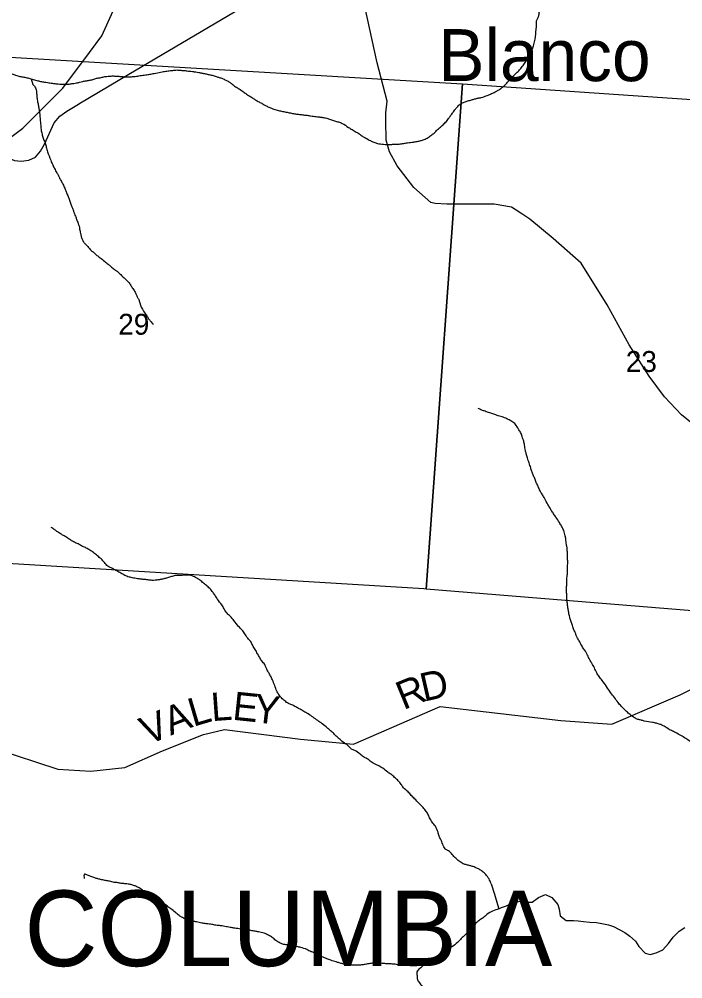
# Model space of a CAD drawing. Extents: x -15 to 405, y -40 to 87.
# Drawn here: x 5.48 to 6.81, y 18.018 to 19.941 of the extents above; entities that cross this region are included whole.
import ezdxf

# ---------------------------------------------------------------- set-up
doc = ezdxf.new("R2010")
doc.units = 0
for name, color, linetype in [('GM_P_State_Location', 7, 'Continuous'), ('GM_X_Adjacent_County_Text', 7, 'Continuous'), ('GM_X_Airport_Location_Class_2', 7, 'Continuous'), ('GM_X_County_Road', 7, 'Continuous'), ('GM_X_County_Road_Text', 7, 'Continuous'), ('GM_X_Minor_River', 7, 'Continuous'), ('GM_X_State_Location', 7, 'Continuous'), ('GM_X_Township_ROW', 7, 'Continuous'), ('GM_X_Township_Text', 7, 'Continuous'), ('GM_X_Unincorporated_Location', 7, 'Continuous')]:
    doc.layers.add(name, color=color, linetype=linetype)

msp = doc.modelspace()

# ---------------------------------------------------------------- linework, layer by layer
at = {"layer": 'GM_P_State_Location'}
msp.add_lwpolyline([(5.4305, 18.4794), (5.557, 18.4381), (5.6234, 18.4343), (5.6914, 18.4412), (5.767, 18.475), (5.8493, 18.5078), (5.8915, 18.518), (6.0434, 18.4984), (6.1497, 18.4886), (6.324, 18.5635), (6.5659, 18.5359), (6.6681, 18.5284), (6.8048, 18.5869), (6.8593, 18.6138)], dxfattribs=at)
at = {"layer": 'GM_X_Adjacent_County_Text'}
for points in [[(5.504, 19.8214), (5.507, 19.8106)], [(6.4257, 18.2083), (6.4324, 18.1875), (6.4386, 18.1672), (6.4414, 18.1583)], [(6.4414, 18.1583), (6.4465, 18.161), (6.4564, 18.164), (6.4696, 18.1701), (6.4833, 18.1739), (6.4954, 18.1717), (6.5083, 18.1717), (6.5211, 18.1812), (6.5348, 18.1869), (6.5477, 18.1809), (6.5594, 18.1669), (6.5621, 18.1574), (6.564, 18.1445), (6.5765, 18.135), (6.5909, 18.1347), (6.6004, 18.1343), (6.611, 18.1328), (6.6239, 18.1317), (6.6371, 18.1306), (6.6481, 18.1287), (6.6614, 18.1265), (6.6712, 18.1227), (6.6826, 18.117), (6.694, 18.1106), (6.7039, 18.1038), (6.7152, 18.0932), (6.7221, 18.083), (6.7346, 18.0693), (6.7448, 18.0667), (6.7569, 18.0698), (6.7698, 18.0758), (6.7812, 18.0888), (6.7906, 18.1013), (6.8027, 18.1134), (6.8145, 18.121)]]:
    msp.add_lwpolyline(points, dxfattribs=at)
for points in [[(6.0573, 19.7487), (6.0641, 19.7474), (6.0751, 19.7459), (6.0811, 19.7453), (6.0879, 19.7443), (6.0962, 19.7429), (6.1041, 19.7403), (6.1116, 19.7374), (6.1199, 19.7353), (6.1274, 19.7324), (6.14, 19.7243), (6.1471, 19.7199), (6.1553, 19.7151), (6.162, 19.7111), (6.1679, 19.7067), (6.1746, 19.7031), (6.1839, 19.6978), (6.1907, 19.6949), (6.1982, 19.6924), (6.2038, 19.6911), (6.2103, 19.6905), (6.2163, 19.6899), (6.2228, 19.6901), (6.2304, 19.6906), (6.2414, 19.691), (6.2509, 19.6922), (6.2582, 19.6935), (6.2643, 19.6944), (6.27, 19.695), (6.2776, 19.6962), (6.2849, 19.6979), (6.2914, 19.6999), (6.2995, 19.7042), (6.3069, 19.7093), (6.3128, 19.7144), (6.3206, 19.7218), (6.3277, 19.728), (6.3347, 19.7346), (6.3407, 19.7424), (6.3447, 19.7479), (6.3494, 19.7542), (6.3542, 19.7609), (6.3589, 19.7665), (6.3656, 19.7723), (6.3718, 19.7752), (6.3794, 19.7776), (6.3867, 19.7796), (6.3928, 19.7813), (6.3997, 19.783), (6.4062, 19.7843), (6.4162, 19.7877), (6.4231, 19.7905), (6.4304, 19.7937), (6.437, 19.7973), (6.4432, 19.8009), (6.4502, 19.8064), (6.4561, 19.8119), (6.4616, 19.8178), (6.4679, 19.8248), (6.4769, 19.8336), (6.4828, 19.8395), (6.4884, 19.8461), (6.494, 19.8543), (6.5, 19.8636), (6.5052, 19.8725), (6.5089, 19.8815), (6.5115, 19.8902), (6.5141, 19.9011), (6.5151, 19.9083), (6.5157, 19.9159), (6.5164, 19.923), (6.517, 19.9299), (6.5168, 19.9363), (6.5189, 19.942), (6.5214, 19.9479), (6.5223, 19.9548), (6.5237, 19.9615), (6.5258, 19.9672), (6.5306, 19.9746), (6.5368, 19.9782), (6.546, 19.9817), (6.5537, 19.9841), (6.5598, 19.9866), (6.5676, 19.9909), (6.5758, 19.9974), (6.5844, 20.0047), (6.5903, 20.0106), (6.597, 20.0187), (6.6013, 20.0243), (6.6046, 20.0299), (6.6086, 20.0381), (6.6108, 20.0456), (6.6121, 20.0517), (6.6127, 20.0577), (6.6122, 20.0653), (6.6117, 20.0726), (6.6107, 20.0783)], [(5.28, 19.8679), (5.2943, 19.8728), (5.3045, 19.8732), (5.314, 19.8736), (5.3205, 19.8742), (5.3277, 19.8736), (5.3348, 19.8714), (5.3416, 19.8689), (5.3516, 19.8637), (5.361, 19.8584), (5.3715, 19.8543), (5.3925, 19.849), (5.4023, 19.8472), (5.4102, 19.845), (5.4238, 19.8415), (5.4313, 19.8397), (5.4411, 19.8379), (5.4487, 19.8361), (5.4569, 19.8336), (5.4652, 19.8314), (5.4727, 19.8293), (5.4814, 19.8267), (5.4893, 19.8253), (5.4968, 19.8235), (5.5055, 19.8209), (5.5149, 19.8184), (5.5228, 19.8166), (5.5304, 19.8152), (5.5364, 19.8142), (5.5466, 19.8127), (5.5553, 19.8117), (5.567, 19.8109), (5.5739, 19.8107), (5.5822, 19.8116), (5.5891, 19.8125), (5.5948, 19.8134), (5.601, 19.8151), (5.6071, 19.8164), (5.6136, 19.8177), (5.6201, 19.8187), (5.6277, 19.8203), (5.635, 19.8227), (5.6423, 19.824), (5.6495, 19.8257), (5.6579, 19.8269), (5.6663, 19.8274), (5.6754, 19.8271), (5.6833, 19.8264), (5.692, 19.8258), (5.7023, 19.8258), (5.7122, 19.8266), (5.7225, 19.8282), (5.7332, 19.8297), (5.7416, 19.831), (5.7507, 19.8326), (5.7633, 19.8352), (5.7691, 19.8361), (5.7782, 19.8377), (5.7877, 19.8386), (5.7961, 19.8394), (5.8037, 19.8388), (5.8124, 19.8381), (5.8211, 19.8371), (5.8272, 19.8365), (5.834, 19.8355), (5.8396, 19.8346), (5.846, 19.8332), (5.8532, 19.8318), (5.8607, 19.8301), (5.8686, 19.8283), (5.8765, 19.8257), (5.8825, 19.824), (5.8889, 19.8215), (5.8956, 19.8183), (5.9012, 19.815), (5.9068, 19.8111), (5.9134, 19.8059), (5.9209, 19.8015), (5.9294, 19.7955), (5.9357, 19.7911), (5.9439, 19.7859), (5.9506, 19.7815), (5.9569, 19.7775), (5.9644, 19.7735), (5.9707, 19.7698), (5.9767, 19.7666), (5.9838, 19.7637), (5.9902, 19.7612), (5.9999, 19.7582), (6.0078, 19.7564), (6.0169, 19.7546), (6.0256, 19.7528), (6.0335, 19.7514), (6.0414, 19.7504), (6.0497, 19.7494), (6.0573, 19.7487)], [(5.507, 19.8106), (5.5111, 19.8056), (5.5142, 19.7971), (5.515, 19.788), (5.5159, 19.78), (5.5175, 19.7715), (5.5191, 19.7635), (5.5204, 19.757), (5.521, 19.7505), (5.5218, 19.7403), (5.5229, 19.7288), (5.5241, 19.7174), (5.5261, 19.709), (5.5285, 19.7009), (5.532, 19.6928), (5.534, 19.6848), (5.5367, 19.6756), (5.543, 19.6587), (5.5469, 19.6494), (5.5508, 19.6417), (5.5551, 19.6336), (5.5587, 19.6274), (5.5615, 19.6216), (5.5654, 19.6142), (5.5694, 19.6065), (5.5725, 19.5988), (5.5753, 19.5919), (5.5789, 19.5842), (5.5813, 19.5765), (5.584, 19.5684), (5.5869, 19.5622), (5.5889, 19.5557), (5.5924, 19.5465), (5.5949, 19.5403), (5.5977, 19.5326), (5.5997, 19.5265), (5.601, 19.5204), (5.6027, 19.512), (5.6043, 19.5051), (5.6068, 19.4989), (5.61, 19.4931), (5.6159, 19.4872), (5.6221, 19.4798), (5.628, 19.4747), (5.6357, 19.4679), (5.642, 19.4632), (5.6513, 19.4557), (5.6579, 19.4501), (5.6635, 19.4458), (5.6701, 19.4402), (5.6761, 19.4362), (5.6816, 19.4311), (5.6882, 19.4244), (5.6956, 19.4177), (5.7014, 19.4107), (5.7054, 19.4049), (5.7101, 19.3975), (5.7137, 19.3909), (5.7161, 19.3851), (5.7194, 19.3793), (5.7214, 19.3728), (5.7292, 19.3558), (5.7346, 19.3484), (5.7382, 19.3422)], [(5.7382, 19.3422), (5.7426, 19.3364), (5.7488, 19.3297)], [(6.5777, 18.7853), (6.5772, 18.7933), (6.5771, 18.802), (6.5777, 18.81), (6.5782, 18.8248), (6.5792, 18.8327), (6.5791, 18.8411), (6.5794, 18.8494), (6.5793, 18.8578), (6.5792, 18.8658), (6.5787, 18.8738), (6.5782, 18.8821), (6.5769, 18.8886), (6.5757, 18.8989), (6.5745, 18.9058), (6.5714, 18.9165), (6.5671, 18.925), (6.5628, 18.9324), (6.5559, 18.9429), (6.5512, 18.9499), (6.5465, 18.9569), (6.5419, 18.965), (6.5379, 18.9716), (6.5322, 18.9828), (6.5279, 18.9894), (6.5239, 18.996), (6.52, 19.0052), (6.5161, 19.013), (6.5133, 19.0207), (6.5102, 19.028), (6.5074, 19.0349), (6.5053, 19.0422), (6.5022, 19.0518), (6.4988, 19.0622), (6.4964, 19.0702), (6.4947, 19.0767), (6.4928, 19.0874), (6.4912, 19.0955), (6.488, 19.1047), (6.4849, 19.1132), (6.4806, 19.1198), (6.4748, 19.1291), (6.4674, 19.135), (6.46, 19.139), (6.4502, 19.1435), (6.4401, 19.1465), (6.4311, 19.1495), (6.4232, 19.152), (6.4138, 19.1554), (6.4071, 19.1579), (6.3999, 19.1608)], [(5.7921, 18.8261), (5.7848, 18.8241), (5.7768, 18.8217), (5.7695, 18.8196), (5.7626, 18.818), (5.7557, 18.8171), (5.7489, 18.8165), (5.7398, 18.8172), (5.7315, 18.8182), (5.7243, 18.8189), (5.7167, 18.8199), (5.7065, 18.8217), (5.6979, 18.8239), (5.6893, 18.8276), (5.6818, 18.832), (5.6736, 18.8365), (5.6643, 18.8414), (5.6557, 18.8466), (5.6492, 18.854), (5.6422, 18.8611), (5.6348, 18.8674), (5.627, 18.8737), (5.6196, 18.8782), (5.6125, 18.8822), (5.605, 18.8855), (5.598, 18.8895), (5.5905, 18.8928), (5.583, 18.8972), (5.5767, 18.9016), (5.57, 18.9056), (5.5637, 18.9093), (5.557, 18.9137), (5.5507, 18.9181), (5.544, 18.9228)], [(6.4257, 18.2083), (6.4229, 18.2156), (6.4168, 18.2253), (6.4098, 18.232), (6.4035, 18.2367), (6.3971, 18.2396), (6.39, 18.2429), (6.3836, 18.2446), (6.3768, 18.2464), (6.3701, 18.2485), (6.3619, 18.2541), (6.3549, 18.2596), (6.3479, 18.2674), (6.3402, 18.2745), (6.3339, 18.2786), (6.3289, 18.2878), (6.325, 18.2971), (6.3218, 18.3037), (6.3194, 18.3117), (6.3141, 18.3237), (6.3076, 18.3322), (6.3025, 18.3408), (6.2993, 18.3477), (6.2943, 18.3555), (6.2881, 18.3629), (6.2818, 18.3692), (6.2723, 18.379), (6.2657, 18.3857), (6.2595, 18.3927), (6.2502, 18.401), (6.2455, 18.4076), (6.2397, 18.4147), (6.2323, 18.4217), (6.2249, 18.4281), (6.2186, 18.4321), (6.209, 18.44), (6.1918, 18.4489), (6.1837, 18.4545), (6.1774, 18.4589), (6.1699, 18.4629), (6.1633, 18.4681), (6.1525, 18.4757), (6.1461, 18.4785), (6.1388, 18.4856), (6.1317, 18.4904), (6.1232, 18.4975), (6.1151, 18.5046), (6.1089, 18.5109), (6.1026, 18.5165), (6.0949, 18.5232), (6.0849, 18.5307), (6.076, 18.5371), (6.0667, 18.5439), (6.0567, 18.5503), (6.0485, 18.5551), (6.041, 18.5592), (6.0347, 18.5628), (6.0261, 18.5672), (6.0197, 18.5697), (6.0123, 18.5749), (6.0057, 18.5808), (6.0002, 18.5875), (5.9963, 18.5948), (5.9921, 18.6056), (5.9875, 18.6171), (5.9836, 18.6249), (5.9797, 18.6322), (5.975, 18.6411), (5.9722, 18.6477), (5.966, 18.6551), (5.9617, 18.6625), (5.9577, 18.6694), (5.9527, 18.6779), (5.948, 18.6857), (5.9448, 18.6926), (5.9379, 18.7009), (5.9321, 18.7094), (5.9263, 18.7172), (5.9197, 18.7242), (5.9102, 18.736), (5.9029, 18.7446), (5.8966, 18.7505), (5.8909, 18.7594), (5.8858, 18.7672), (5.8775, 18.7788), (5.8728, 18.7858), (5.8684, 18.7924), (5.8619, 18.8002), (5.8552, 18.8062), (5.8475, 18.8125), (5.8404, 18.8184), (5.8311, 18.8237), (5.8248, 18.8265), (5.8145, 18.8269), (5.8081, 18.8267), (5.7993, 18.8262), (5.7921, 18.8261)], [(7.1039, 18.1457), (7.1065, 18.169), (7.1065, 18.1789), (7.1059, 18.1853), (7.1058, 18.1922), (7.1061, 18.2017), (7.1051, 18.2177), (7.1032, 18.2276), (7.1002, 18.2414), (7.0975, 18.2517), (7.0952, 18.2621), (7.0915, 18.2751), (7.0883, 18.2836), (7.0827, 18.2967), (7.0788, 18.3044), (7.0752, 18.311), (7.0709, 18.318), (7.0662, 18.3253), (7.0611, 18.3331), (7.0553, 18.3413), (7.0506, 18.3479), (7.0444, 18.3553), (7.0356, 18.3659), (7.029, 18.3737), (7.0226, 18.3838), (7.0178, 18.3904), (7.0113, 18.3982), (7.0032, 18.4065), (6.9947, 18.4151), (6.9877, 18.421), (6.9773, 18.4282), (6.9699, 18.4326), (6.9595, 18.4391), (6.952, 18.4423), (6.9438, 18.4479), (6.9375, 18.4516), (6.93, 18.456), (6.9229, 18.4596), (6.9158, 18.4603), (6.9078, 18.4609), (6.8995, 18.4608), (6.893, 18.4614), (6.885, 18.4613), (6.8786, 18.4607), (6.8714, 18.4617), (6.8613, 18.4678), (6.8547, 18.4729), (6.8472, 18.4777), (6.8409, 18.4821), (6.8343, 18.4877), (6.825, 18.4937), (6.8161, 18.4997), (6.806, 18.5057), (6.7956, 18.5114), (6.7874, 18.5154), (6.7784, 18.5207), (6.771, 18.5251), (6.7646, 18.528), (6.7571, 18.5301), (6.7496, 18.5319), (6.733, 18.5347), (6.7266, 18.5364), (6.7202, 18.5378), (6.7134, 18.5411), (6.7045, 18.5474), (6.6972, 18.5538), (6.6869, 18.5643), (6.6803, 18.5718), (6.6734, 18.5815), (6.6654, 18.592), (6.6571, 18.6037), (6.6484, 18.6162), (6.6422, 18.624), (6.6375, 18.6313), (6.6329, 18.6414), (6.6279, 18.6503), (6.6235, 18.6576), (6.6193, 18.6669), (6.6132, 18.677), (6.6081, 18.6847), (6.6035, 18.6932), (6.5992, 18.7006), (6.5942, 18.7122), (6.5911, 18.7195), (6.5883, 18.7279), (6.5855, 18.7356), (6.5835, 18.7429), (6.5815, 18.7521), (6.5802, 18.7597), (6.579, 18.7681), (6.5781, 18.7761), (6.5777, 18.7853)], [(6.2909, 18.0451), (6.2848, 18.0458), (6.2764, 18.0441), (6.2665, 18.0441), (6.2582, 18.0447), (6.2502, 18.0454), (6.2434, 18.0456), (6.2336, 18.0471), (6.2253, 18.0477), (6.2184, 18.048), (6.2109, 18.0486), (6.198, 18.0494), (6.19, 18.0493), (6.1805, 18.0481), (6.1713, 18.0465), (6.1641, 18.0456), (6.1576, 18.0454), (6.1489, 18.0453), (6.1424, 18.0459), (6.1356, 18.0465), (6.1288, 18.0479), (6.1213, 18.05), (6.1149, 18.0518), (6.1044, 18.0551), (6.0965, 18.0581), (6.0868, 18.0622), (6.0782, 18.067), (6.0715, 18.0703), (6.0651, 18.0724), (6.0565, 18.0765), (6.0441, 18.0807), (6.037, 18.0825), (6.0291, 18.0846), (6.0193, 18.0861), (6.0098, 18.0868), (6.003, 18.0893), (5.9941, 18.0949), (5.9871, 18.1008), (5.9797, 18.1053), (5.9707, 18.1094), (5.9594, 18.112), (5.953, 18.1134), (5.9443, 18.1148), (5.9345, 18.1163), (5.9235, 18.1178), (5.9122, 18.1196), (5.905, 18.1206), (5.8952, 18.1225), (5.8835, 18.1244), (5.874, 18.1255), (5.8661, 18.1269), (5.8548, 18.1284), (5.8457, 18.1298), (5.8352, 18.1321), (5.8284, 18.1331), (5.8208, 18.1348), (5.8141, 18.1373), (5.8073, 18.1406), (5.8003, 18.145), (5.7929, 18.151), (5.7836, 18.1585), (5.7762, 18.164), (5.7685, 18.1704), (5.7592, 18.1768), (5.7506, 18.182), (5.7429, 18.1876), (5.7354, 18.192), (5.7279, 18.1953), (5.7205, 18.2001), (5.7138, 18.2034), (5.7074, 18.2058), (5.7002, 18.2076), (5.6915, 18.2086), (5.684, 18.2093), (5.6772, 18.2106), (5.6704, 18.2112), (5.661, 18.2135), (5.6538, 18.2148), (5.6447, 18.2167), (5.6376, 18.2184), (5.6312, 18.2201), (5.6233, 18.2231), (5.6169, 18.2256), (5.6106, 18.2277), (5.6103, 18.2189)], [(6.4414, 18.1583), (6.4176, 18.147), (6.4098, 18.1404), (6.4028, 18.1357), (6.3961, 18.1302), (6.3899, 18.1236), (6.3847, 18.1173), (6.3777, 18.1103), (6.3718, 18.104), (6.3643, 18.0971), (6.3561, 18.0886), (6.344, 18.0803), (6.3374, 18.0755), (6.3277, 18.0683), (6.3203, 18.0647), (6.3126, 18.06), (6.3052, 18.0553), (6.2971, 18.0495), (6.2905, 18.0448), (6.283, 18.0386), (6.2771, 18.0319), (6.2773, 18.0247), (6.2781, 18.0167), (6.2821, 18.0101), (6.2879, 18.0023), (6.2929, 17.9915), (6.2979, 17.9838), (6.3007, 17.9768), (6.3039, 17.9687), (6.3078, 17.961), (6.311, 17.9545), (6.3138, 17.9479), (6.317, 17.9406), (6.3194, 17.934), (6.3241, 17.9248), (6.3269, 17.9178), (6.3289, 17.9113), (6.3313, 17.9029)]]:
    msp.add_spline(points, degree=3, dxfattribs=at)
at = {"layer": 'GM_X_Airport_Location_Class_2'}
for points in [[(6.3688, 19.8114), (6.2955, 18.7989), (6.2908, 18.7993), (5.28, 18.8608), (5.3465, 19.8721)], [(6.3688, 19.8114), (7.3949, 19.7416), (7.3224, 18.7155), (6.2955, 18.7989)]]:
    msp.add_lwpolyline(points, close=True, dxfattribs=at)
at = {"layer": 'GM_X_State_Location'}
for points in [[(5.6204, 19.8745), (5.6452, 19.908), (5.7984, 20.246), (5.8576, 20.3778), (6.0106, 20.7189), (6.0897, 20.8941)], [(4.8734, 19.3513), (4.9332, 19.3808), (5.2102, 19.5467), (5.4005, 19.659), (5.4339, 19.6835), (5.4873, 19.7225), (5.5672, 19.8027), (5.6204, 19.8745)]]:
    msp.add_lwpolyline(points, dxfattribs=at)
at = {"layer": 'GM_X_Township_Text'}
for points in [[(5.5987, 19.771), (5.5992, 19.7713), (5.6997, 19.8308), (5.9115, 19.9562), (6.1383, 20.0943)], [(5.2723, 19.6212), (5.3223, 19.6433), (5.3458, 19.6658), (5.3621, 19.6821), (5.3746, 19.6933), (5.3872, 19.6992), (5.3981, 19.699), (5.4092, 19.6962), (5.4339, 19.6835), (5.459, 19.6624), (5.4705, 19.6577), (5.4837, 19.6567), (5.4992, 19.6589), (5.5125, 19.6647), (5.5227, 19.6767), (5.5304, 19.6906), (5.5497, 19.7338), (5.5611, 19.7471), (5.5751, 19.757), (5.5987, 19.771)]]:
    msp.add_lwpolyline(points, dxfattribs=at)
at = {"layer": 'GM_X_Unincorporated_Location'}
msp.add_lwpolyline([(6.8471, 19.1163), (6.8076, 19.1485), (6.7734, 19.1842), (6.7425, 19.2259), (6.7023, 19.2885), (6.6588, 19.3685), (6.6062, 19.4521), (6.5505, 19.502), (6.5034, 19.5405), (6.4854, 19.5528), (6.4667, 19.5644), (6.432, 19.5704), (6.3773, 19.5706), (6.3371, 19.5705), (6.3135, 19.5721), (6.3048, 19.5739), (6.271, 19.6039), (6.2375, 19.6475), (6.2219, 19.6754), (6.2156, 19.6985), (6.2151, 19.7372), (6.2149, 19.7535), (6.2172, 19.7772), (6.1974, 19.8539), (6.1525, 20.0587)], dxfattribs=at)

# ---------------------------------------------------------------- texts
at = {"layer": 'GM_X_County_Road'}
for s, p in [('29', (5.6784, 19.3089)), ('23', (6.6959, 19.2343))]:
    msp.add_text(s, height=0.04186, rotation=0, dxfattribs=at).set_placement(p)
at = {"layer": 'GM_X_County_Road_Text'}
msp.add_text('COLUMBIA', height=0.15152, rotation=0, dxfattribs=at).set_placement((5.4904, 18.0434))
at = {"layer": 'GM_X_Minor_River'}
for s, rotation, p in [('D', 12.8947, (6.291, 18.5732)), ('R', 22.2935, (6.2501, 18.5562)), ('L', 16.4369, (5.8285, 18.5229)), ('L', 4.0618, (5.8661, 18.5343)), ('E', 354.1014, (5.9059, 18.5374)), ('Y', 353.1425, (5.9479, 18.533)), ('A', 21.3056, (5.7831, 18.5051)), ('V', 22.9345, (5.7375, 18.4858))]:
    msp.add_text(s, height=0.0568, rotation=rotation, dxfattribs=at).set_placement(p)
at = {"layer": 'GM_X_Township_ROW'}
msp.add_text('Blanco', height=0.10417, rotation=0, dxfattribs=at).set_placement((6.3197, 19.8171))

doc.saveas('drawing.dxf')
